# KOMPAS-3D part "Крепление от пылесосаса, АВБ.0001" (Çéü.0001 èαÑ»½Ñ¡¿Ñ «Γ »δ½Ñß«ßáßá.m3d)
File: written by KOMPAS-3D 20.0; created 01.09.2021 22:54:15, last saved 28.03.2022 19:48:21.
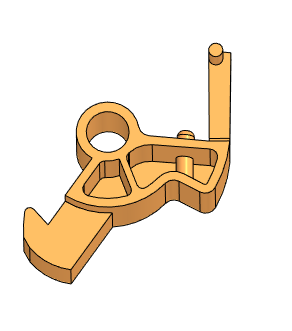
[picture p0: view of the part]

Document properties: Полное имя файла: C:\Users\Sergey\Desktop\для щетки\АВБ.0001 Крепление от пылесосаса.m3d

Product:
- Part/product: Крепление от пылесосаса  | designation АВБ.0001
    Масса: 0.0269358
  - Body: Тело 1
      Масса: 0.0369067

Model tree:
1. Эскиз:1
2. Эскиз:2
3. Элемент выдавливания:1
     Расстояние 1 = 12
4. Эскиз:3  (with: Элемент выдавливания:1)
5. Элемент выдавливания:2
     Расстояние 1 = 3.5
6. Эскиз:4  (with: Элемент выдавливания:1)
7. Элемент выдавливания:3
     Расстояние 2 = 10
8. Эскиз:5  (with: Элемент выдавливания:3)
9. Элемент выдавливания:4  (with: Элемент выдавливания:1)
     Расстояние 1 = 3; Расстояние 2 = 9
10. Эскиз:6  (with: Элемент выдавливания:1)
11. Элемент выдавливания:5
     Расстояние 2 = 3.5
12. Скругление:1  (with: Элемент выдавливания:2)
     Радиус = 1
13. Эскиз:7  (with: Элемент выдавливания:1)
14. Элемент выдавливания:6
     Расстояние 2 = 10
15. Элемент выдавливания:7  (with: Элемент выдавливания:2, Элемент выдавливания:6)
     Расстояние 1 = -6.4987
16. Эскиз:8  (with: Элемент выдавливания:1)
17. Элемент выдавливания:8  (with: Элемент выдавливания:1)
     Толщина стенки 1 = 1.2; Расстояние 1 = -12
18. Скругление:2  (with: Элемент выдавливания:8, Элемент выдавливания:6)
     Радиус = 1
19. Скругление:3  (with: Элемент выдавливания:3)
     Радиус = 2

Referenced files in C:\Users\Sergey\Desktop\для щетки\: SKM_22722032815310 — копия.jpg
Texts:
  АВБ.0001
  SKM_22722032815310 — копия.jpg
